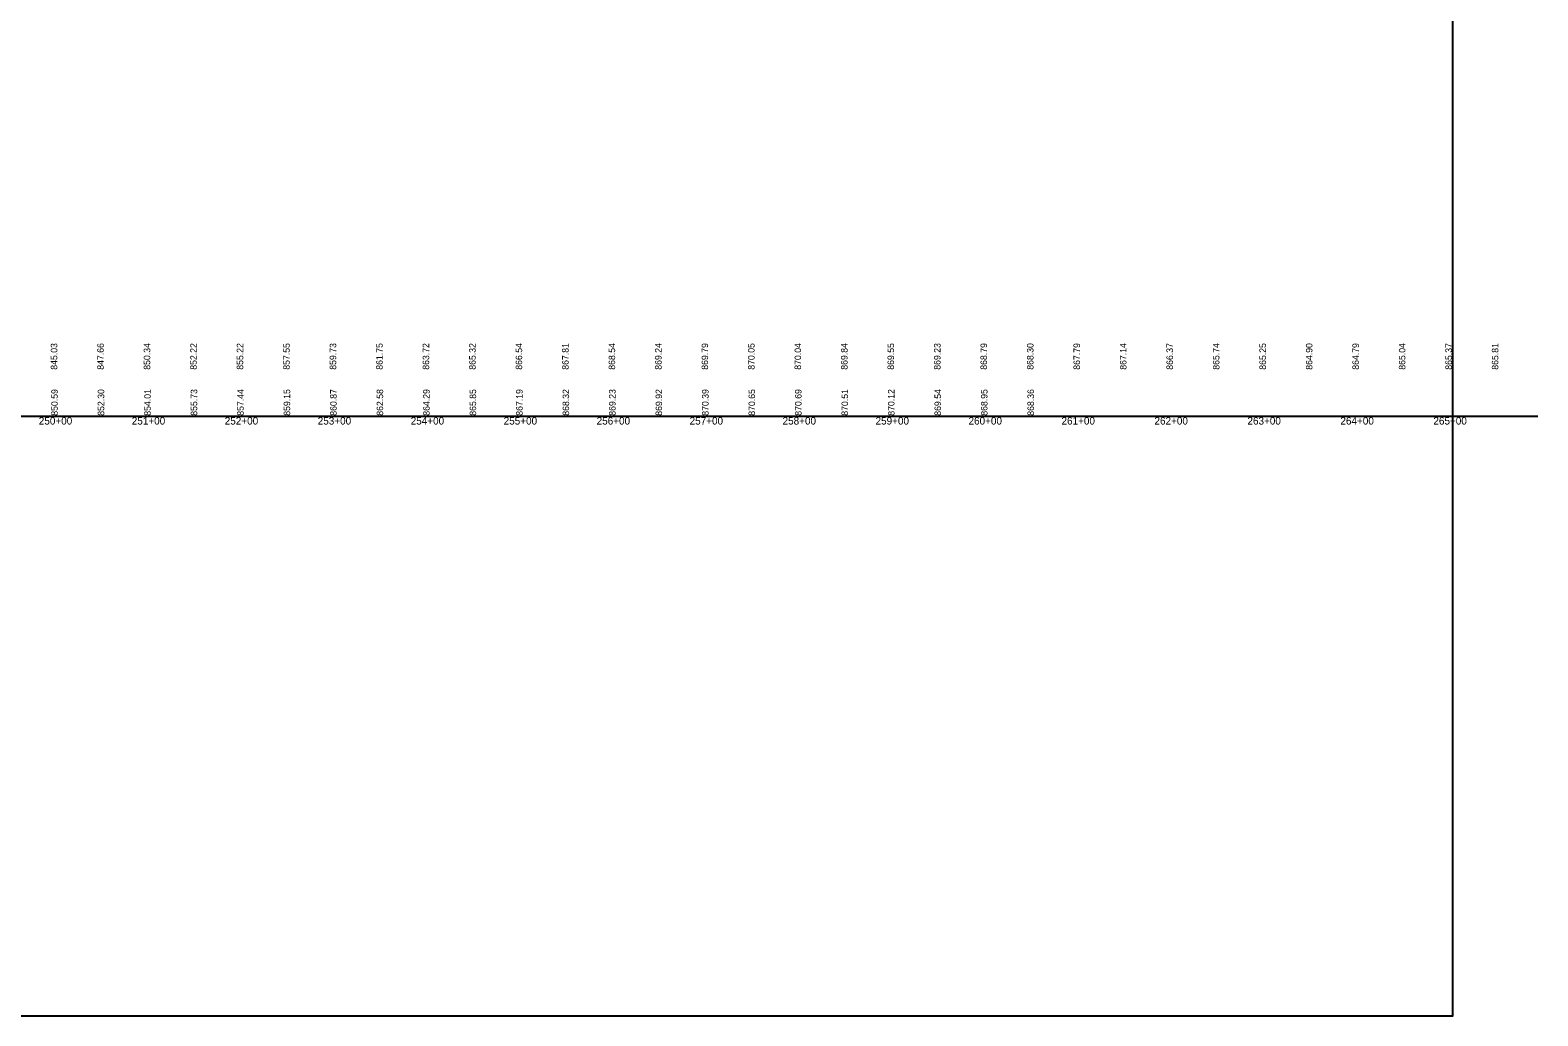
# Model space of a CAD drawing. Extents: x 1475945 to 1495590, y 1094511 to 1111511.
# Drawn here: x 1493933 to 1495555, y 1094866 to 1095927 of the extents above; entities that cross this region are included whole.
import ezdxf

# ---------------------------------------------------------------- set-up
doc = ezdxf.new("R2010")
doc.units = 0
for name, color, linetype in [('RD_DDB_StaTX', 7, 'Continuous'), ('RD_DDB_StripGrade', 7, 'Continuous'), ('RD_GPK_Profile_Cell', 7, 'Continuous'), ('RD_Sketch7', 7, 'Continuous')]:
    doc.layers.add(name, color=color, linetype=linetype)

msp = doc.modelspace()

# ---------------------------------------------------------------- linework, layer by layer
at = {"layer": 'RD_GPK_Profile_Cell'}
msp.add_line((1491570.9, 1095511.2), (1495554.8, 1095511.2), dxfattribs=at)
at = {"layer": 'RD_Sketch7'}
msp.add_lwpolyline([(1491863.3, 1094866), (1495463.3, 1094866), (1495463.3, 1097066), (1491863.3, 1097066)], close=True, dxfattribs=at)

# ---------------------------------------------------------------- texts
at = {"layer": 'RD_DDB_StaTX'}
for s, p in [('250+00', (1493942.4, 1095502.2)), ('251+00', (1494042.4, 1095502.2)), ('252+00', (1494142.4, 1095502.2)), ('253+00', (1494242.4, 1095502.2)), ('254+00', (1494342.4, 1095502.2)), ('255+00', (1494442.4, 1095502.2)), ('256+00', (1494542.4, 1095502.2)), ('257+00', (1494642.4, 1095502.2)), ('258+00', (1494742.4, 1095502.2)), ('259+00', (1494842.4, 1095502.2)), ('260+00', (1494942.4, 1095502.2)), ('261+00', (1495042.4, 1095502.2)), ('262+00', (1495142.4, 1095502.2)), ('263+00', (1495242.4, 1095502.2)), ('264+00', (1495342.4, 1095502.2)), ('265+00', (1495442.4, 1095502.2))]:
    msp.add_text(s, height=8, dxfattribs=at).set_placement(p)
at = {"layer": 'RD_DDB_StripGrade'}
for s, p in [('845.03', (1493962.3, 1095561.2)), ('847.66', (1494012.3, 1095561.2)), ('850.34', (1494062.3, 1095561.2)), ('852.22', (1494112.3, 1095561.2)), ('855.22', (1494162.3, 1095561.2)), ('857.55', (1494212.3, 1095561.2)), ('859.73', (1494262.3, 1095561.2)), ('861.75', (1494312.3, 1095561.2)), ('863.72', (1494362.3, 1095561.2)), ('865.32', (1494412.3, 1095561.2)), ('866.54', (1494462.3, 1095561.2)), ('867.81', (1494512.3, 1095561.2)), ('868.54', (1494562.3, 1095561.2)), ('869.24', (1494612.3, 1095561.2)), ('869.79', (1494662.3, 1095561.2)), ('870.05', (1494712.3, 1095561.2)), ('870.04', (1494762.3, 1095561.2)), ('869.84', (1494812.3, 1095561.2)), ('869.55', (1494862.3, 1095561.2)), ('869.23', (1494912.3, 1095561.2)), ('868.79', (1494962.3, 1095561.2)), ('868.30', (1495012.3, 1095561.2)), ('867.79', (1495062.3, 1095561.2)), ('867.14', (1495112.3, 1095561.2)), ('866.37', (1495162.3, 1095561.2)), ('865.74', (1495212.3, 1095561.2)), ('865.25', (1495262.3, 1095561.2)), ('864.90', (1495312.3, 1095561.2)), ('864.79', (1495362.3, 1095561.2)), ('865.04', (1495412.3, 1095561.2)), ('865.37', (1495462.3, 1095561.2)), ('865.81', (1495512.3, 1095561.2)), ('850.59', (1493962.8, 1095511.7)), ('852.30', (1494012.8, 1095511.7)), ('854.01', (1494062.8, 1095511.7)), ('855.73', (1494112.8, 1095511.7)), ('857.44', (1494162.8, 1095511.7)), ('859.15', (1494212.8, 1095511.7)), ('860.87', (1494262.8, 1095511.7)), ('862.58', (1494312.8, 1095511.7)), ('864.29', (1494362.8, 1095511.7)), ('865.85', (1494412.8, 1095511.7)), ('867.19', (1494462.8, 1095511.7)), ('868.32', (1494512.8, 1095511.7)), ('869.23', (1494562.8, 1095511.7)), ('869.92', (1494612.8, 1095511.7)), ('870.39', (1494662.8, 1095511.7)), ('870.65', (1494712.8, 1095511.7)), ('870.69', (1494762.8, 1095511.7)), ('870.51', (1494812.8, 1095511.7)), ('870.12', (1494862.8, 1095511.7)), ('869.54', (1494912.8, 1095511.7)), ('868.95', (1494962.8, 1095511.7)), ('868.36', (1495012.8, 1095511.7))]:
    msp.add_text(s, height=7, rotation=90, dxfattribs=at).set_placement(p)

doc.saveas('drawing.dxf')
